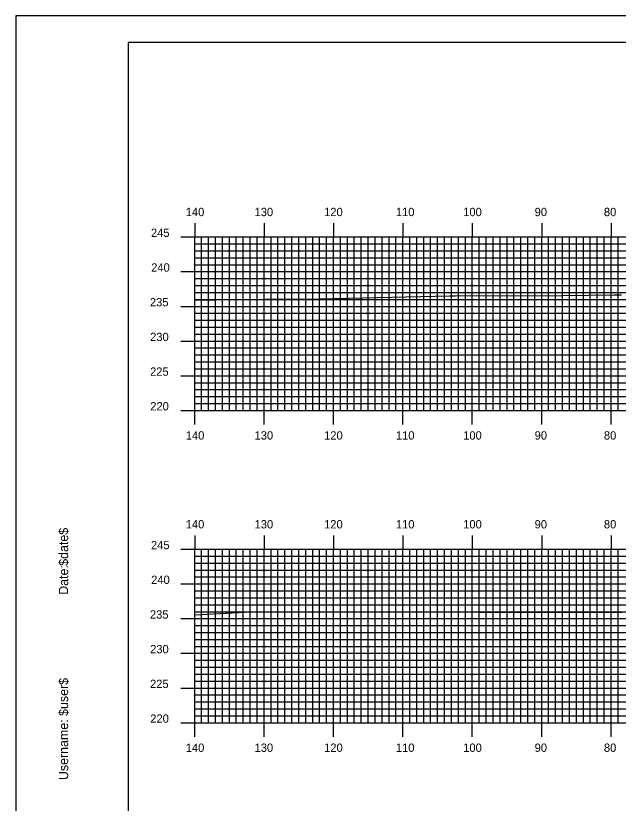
# Model space of a CAD drawing. Extents: x 1802716 to 1803060, y 442591 to 442811.
# Drawn here: x 1802716.3 to 1802803.1, y 442697.1 to 442810.5 of the extents above; entities that cross this region are included whole.
import ezdxf

# ---------------------------------------------------------------- set-up
doc = ezdxf.new("R2010")
doc.units = 0
for name, color, linetype in [('BORDER', 7, 'Continuous'), ('H_V ANNOTATION', 7, 'Continuous'), ('MAJOR', 7, 'Continuous'), ('MINOR', 7, 'Continuous'), ('PLOT BOUNDARY', 7, 'Continuous'), ('S_Roadway_Centerline', 7, 'Continuous')]:
    doc.layers.add(name, color=color, linetype=linetype)

msp = doc.modelspace()

# ---------------------------------------------------------------- linework, layer by layer
at = {"layer": 'BORDER'}
msp.add_lwpolyline([(1802732.51, 442596.67), (1803052.51, 442596.67), (1803052.51, 442806.67), (1802732.51, 442806.67)], close=True, dxfattribs=at)
at = {"layer": 'MAJOR'}
for p, q in [((1802742.11, 442780.67), (1802742.11, 442778.67)), ((1802752.11, 442780.67), (1802752.11, 442778.67)), ((1802762.11, 442780.67), (1802762.11, 442778.67)), ((1802772.11, 442780.67), (1802772.11, 442778.67)), ((1802782.11, 442780.67), (1802782.11, 442778.67)), ((1802792.11, 442780.67), (1802792.11, 442778.67)), ((1802802.11, 442780.67), (1802802.11, 442778.67)), ((1802740.11, 442778.67), (1802742.11, 442778.67)), ((1802742.11, 442778.67), (1803022.11, 442778.67)), ((1802742.11, 442753.67), (1802742.11, 442778.67)), ((1802742.11, 442753.67), (1802742.11, 442778.67)), ((1802742.11, 442778.67), (1803022.11, 442778.67)), ((1802752.11, 442753.67), (1802752.11, 442778.67)), ((1802762.11, 442753.67), (1802762.11, 442778.67)), ((1802772.11, 442753.67), (1802772.11, 442778.67)), ((1802782.11, 442753.67), (1802782.11, 442778.67)), ((1802792.11, 442753.67), (1802792.11, 442778.67)), ((1802802.11, 442753.67), (1802802.11, 442778.67)), ((1802740.11, 442773.67), (1802742.11, 442773.67)), ((1802742.11, 442773.67), (1803022.11, 442773.67)), ((1802740.11, 442768.67), (1802742.11, 442768.67)), ((1802742.11, 442768.67), (1803022.11, 442768.67)), ((1802740.11, 442763.67), (1802742.11, 442763.67)), ((1802742.11, 442763.67), (1803022.11, 442763.67)), ((1802740.11, 442758.67), (1802742.11, 442758.67)), ((1802742.11, 442758.67), (1803022.11, 442758.67)), ((1802740.11, 442753.67), (1802742.11, 442753.67)), ((1802742.11, 442753.67), (1803022.11, 442753.67)), ((1802742.11, 442753.67), (1803022.11, 442753.67)), ((1802742.11, 442751.66), (1802742.11, 442753.67)), ((1802752.11, 442751.66), (1802752.11, 442753.67)), ((1802762.11, 442751.66), (1802762.11, 442753.67)), ((1802772.11, 442751.66), (1802772.11, 442753.67)), ((1802782.11, 442751.66), (1802782.11, 442753.67)), ((1802792.11, 442751.66), (1802792.11, 442753.67)), ((1802802.11, 442751.66), (1802802.11, 442753.67)), ((1802742.11, 442735.67), (1802742.11, 442733.67)), ((1802752.11, 442735.67), (1802752.11, 442733.67)), ((1802762.11, 442735.67), (1802762.11, 442733.67)), ((1802772.11, 442735.67), (1802772.11, 442733.67)), ((1802782.11, 442735.67), (1802782.11, 442733.67)), ((1802792.11, 442735.67), (1802792.11, 442733.67)), ((1802802.11, 442735.67), (1802802.11, 442733.67)), ((1802740.11, 442733.67), (1802742.11, 442733.67)), ((1802742.11, 442733.67), (1803022.11, 442733.67)), ((1802742.11, 442708.67), (1802742.11, 442733.67)), ((1802742.11, 442708.67), (1802742.11, 442733.67)), ((1802742.11, 442733.67), (1803022.11, 442733.67)), ((1802752.11, 442708.67), (1802752.11, 442733.67)), ((1802762.11, 442708.67), (1802762.11, 442733.67)), ((1802772.11, 442708.67), (1802772.11, 442733.67)), ((1802782.11, 442708.67), (1802782.11, 442733.67)), ((1802792.11, 442708.67), (1802792.11, 442733.67)), ((1802802.11, 442708.67), (1802802.11, 442733.67)), ((1802740.11, 442728.67), (1802742.11, 442728.67)), ((1802742.11, 442728.67), (1803022.11, 442728.67)), ((1802740.11, 442723.67), (1802742.11, 442723.67)), ((1802742.11, 442723.67), (1803022.11, 442723.67)), ((1802740.11, 442718.67), (1802742.11, 442718.67)), ((1802742.11, 442718.67), (1803022.11, 442718.67)), ((1802740.11, 442713.67), (1802742.11, 442713.67)), ((1802742.11, 442713.67), (1803022.11, 442713.67)), ((1802740.11, 442708.67), (1802742.11, 442708.67)), ((1802742.11, 442708.67), (1803022.11, 442708.67)), ((1802742.11, 442708.67), (1803022.11, 442708.67)), ((1802742.11, 442706.66), (1802742.11, 442708.67)), ((1802752.11, 442706.66), (1802752.11, 442708.67)), ((1802762.11, 442706.66), (1802762.11, 442708.67)), ((1802772.11, 442706.66), (1802772.11, 442708.67)), ((1802782.11, 442706.66), (1802782.11, 442708.67)), ((1802792.11, 442706.66), (1802792.11, 442708.67)), ((1802802.11, 442706.66), (1802802.11, 442708.67))]:
    msp.add_line(p, q, dxfattribs=at)
at = {"layer": 'MINOR'}
for p, q in [((1802743.11, 442753.67), (1802743.11, 442778.67)), ((1802744.11, 442753.67), (1802744.11, 442778.67)), ((1802745.11, 442753.67), (1802745.11, 442778.67)), ((1802746.11, 442753.67), (1802746.11, 442778.67)), ((1802747.11, 442753.67), (1802747.11, 442778.67)), ((1802748.11, 442753.67), (1802748.11, 442778.67)), ((1802749.11, 442753.67), (1802749.11, 442778.67)), ((1802750.11, 442753.67), (1802750.11, 442778.67)), ((1802751.11, 442753.67), (1802751.11, 442778.67)), ((1802753.11, 442753.67), (1802753.11, 442778.67)), ((1802754.11, 442753.67), (1802754.11, 442778.67)), ((1802755.11, 442753.67), (1802755.11, 442778.67)), ((1802756.11, 442753.67), (1802756.11, 442778.67)), ((1802757.11, 442753.67), (1802757.11, 442778.67)), ((1802758.11, 442753.67), (1802758.11, 442778.67)), ((1802759.11, 442753.67), (1802759.11, 442778.67)), ((1802760.11, 442753.67), (1802760.11, 442778.67)), ((1802761.11, 442753.67), (1802761.11, 442778.67)), ((1802763.11, 442753.67), (1802763.11, 442778.67)), ((1802764.11, 442753.67), (1802764.11, 442778.67)), ((1802765.11, 442753.67), (1802765.11, 442778.67)), ((1802766.11, 442753.67), (1802766.11, 442778.67)), ((1802767.11, 442753.67), (1802767.11, 442778.67)), ((1802768.11, 442753.67), (1802768.11, 442778.67)), ((1802769.11, 442753.67), (1802769.11, 442778.67)), ((1802770.11, 442753.67), (1802770.11, 442778.67)), ((1802771.11, 442753.67), (1802771.11, 442778.67)), ((1802773.11, 442753.67), (1802773.11, 442778.67)), ((1802774.11, 442753.67), (1802774.11, 442778.67)), ((1802775.11, 442753.67), (1802775.11, 442778.67)), ((1802776.11, 442753.67), (1802776.11, 442778.67)), ((1802777.11, 442753.67), (1802777.11, 442778.67)), ((1802778.11, 442753.67), (1802778.11, 442778.67)), ((1802779.11, 442753.67), (1802779.11, 442778.67)), ((1802780.11, 442753.67), (1802780.11, 442778.67)), ((1802781.11, 442753.67), (1802781.11, 442778.67)), ((1802783.11, 442753.67), (1802783.11, 442778.67)), ((1802784.11, 442753.67), (1802784.11, 442778.67)), ((1802785.11, 442753.67), (1802785.11, 442778.67)), ((1802786.11, 442753.67), (1802786.11, 442778.67)), ((1802787.11, 442753.67), (1802787.11, 442778.67)), ((1802788.11, 442753.67), (1802788.11, 442778.67)), ((1802789.11, 442753.67), (1802789.11, 442778.67)), ((1802790.11, 442753.67), (1802790.11, 442778.67)), ((1802791.11, 442753.67), (1802791.11, 442778.67)), ((1802793.11, 442753.67), (1802793.11, 442778.67)), ((1802794.11, 442753.67), (1802794.11, 442778.67)), ((1802795.11, 442753.67), (1802795.11, 442778.67)), ((1802796.11, 442753.67), (1802796.11, 442778.67)), ((1802797.11, 442753.67), (1802797.11, 442778.67)), ((1802798.11, 442753.67), (1802798.11, 442778.67)), ((1802799.11, 442753.67), (1802799.11, 442778.67)), ((1802800.11, 442753.67), (1802800.11, 442778.67)), ((1802801.11, 442753.67), (1802801.11, 442778.67)), ((1802803.11, 442753.67), (1802803.11, 442778.67)), ((1802742.11, 442777.67), (1803022.11, 442777.67)), ((1802742.11, 442777.67), (1802744.12, 442777.67)), ((1802742.11, 442776.67), (1803022.11, 442776.67)), ((1802742.11, 442776.67), (1802744.12, 442776.67)), ((1802742.11, 442775.67), (1803022.11, 442775.67)), ((1802742.11, 442775.67), (1802744.12, 442775.67)), ((1802742.11, 442774.67), (1803022.11, 442774.67)), ((1802742.11, 442774.67), (1802744.12, 442774.67)), ((1802742.11, 442772.67), (1803022.11, 442772.67)), ((1802742.11, 442772.67), (1802744.12, 442772.67)), ((1802742.11, 442771.67), (1803022.11, 442771.67)), ((1802742.11, 442771.67), (1802744.12, 442771.67)), ((1802742.11, 442770.67), (1803022.11, 442770.67)), ((1802742.11, 442770.67), (1802744.12, 442770.67)), ((1802742.11, 442769.67), (1803022.11, 442769.67)), ((1802742.11, 442769.67), (1802744.12, 442769.67)), ((1802742.11, 442767.67), (1803022.11, 442767.67)), ((1802742.11, 442767.67), (1802744.12, 442767.67)), ((1802742.11, 442766.67), (1803022.11, 442766.67)), ((1802742.11, 442766.67), (1802744.12, 442766.67)), ((1802742.11, 442765.67), (1803022.11, 442765.67)), ((1802742.11, 442765.67), (1802744.12, 442765.67)), ((1802742.11, 442764.67), (1803022.11, 442764.67)), ((1802742.11, 442764.67), (1802744.12, 442764.67)), ((1802742.11, 442762.67), (1803022.11, 442762.67)), ((1802742.11, 442762.67), (1802744.12, 442762.67)), ((1802742.11, 442761.67), (1803022.11, 442761.67)), ((1802742.11, 442761.67), (1802744.12, 442761.67)), ((1802742.11, 442760.67), (1803022.11, 442760.67)), ((1802742.11, 442760.67), (1802744.12, 442760.67)), ((1802742.11, 442759.67), (1803022.11, 442759.67)), ((1802742.11, 442759.67), (1802744.12, 442759.67)), ((1802742.11, 442757.67), (1803022.11, 442757.67)), ((1802742.11, 442757.67), (1802744.12, 442757.67)), ((1802742.11, 442756.67), (1803022.11, 442756.67)), ((1802742.11, 442756.67), (1802744.12, 442756.67)), ((1802742.11, 442755.67), (1803022.11, 442755.67)), ((1802742.11, 442755.67), (1802744.12, 442755.67)), ((1802742.11, 442754.67), (1803022.11, 442754.67)), ((1802742.11, 442754.67), (1802744.12, 442754.67)), ((1802742.11, 442732.67), (1803022.11, 442732.67)), ((1802742.11, 442732.67), (1802744.12, 442732.67)), ((1802743.11, 442708.67), (1802743.11, 442733.67)), ((1802744.11, 442708.67), (1802744.11, 442733.67)), ((1802745.11, 442708.67), (1802745.11, 442733.67)), ((1802746.11, 442708.67), (1802746.11, 442733.67)), ((1802747.11, 442708.67), (1802747.11, 442733.67)), ((1802748.11, 442708.67), (1802748.11, 442733.67)), ((1802749.11, 442708.67), (1802749.11, 442733.67)), ((1802750.11, 442708.67), (1802750.11, 442733.67)), ((1802751.11, 442708.67), (1802751.11, 442733.67)), ((1802753.11, 442708.67), (1802753.11, 442733.67)), ((1802754.11, 442708.67), (1802754.11, 442733.67)), ((1802755.11, 442708.67), (1802755.11, 442733.67)), ((1802756.11, 442708.67), (1802756.11, 442733.67)), ((1802757.11, 442708.67), (1802757.11, 442733.67)), ((1802758.11, 442708.67), (1802758.11, 442733.67)), ((1802759.11, 442708.67), (1802759.11, 442733.67)), ((1802760.11, 442708.67), (1802760.11, 442733.67)), ((1802761.11, 442708.67), (1802761.11, 442733.67)), ((1802763.11, 442708.67), (1802763.11, 442733.67)), ((1802764.11, 442708.67), (1802764.11, 442733.67)), ((1802765.11, 442708.67), (1802765.11, 442733.67)), ((1802766.11, 442708.67), (1802766.11, 442733.67)), ((1802767.11, 442708.67), (1802767.11, 442733.67)), ((1802768.11, 442708.67), (1802768.11, 442733.67)), ((1802769.11, 442708.67), (1802769.11, 442733.67)), ((1802770.11, 442708.67), (1802770.11, 442733.67)), ((1802771.11, 442708.67), (1802771.11, 442733.67)), ((1802773.11, 442708.67), (1802773.11, 442733.67)), ((1802774.11, 442708.67), (1802774.11, 442733.67)), ((1802775.11, 442708.67), (1802775.11, 442733.67)), ((1802776.11, 442708.67), (1802776.11, 442733.67)), ((1802777.11, 442708.67), (1802777.11, 442733.67)), ((1802778.11, 442708.67), (1802778.11, 442733.67)), ((1802779.11, 442708.67), (1802779.11, 442733.67)), ((1802780.11, 442708.67), (1802780.11, 442733.67)), ((1802781.11, 442708.67), (1802781.11, 442733.67)), ((1802783.11, 442708.67), (1802783.11, 442733.67)), ((1802784.11, 442708.67), (1802784.11, 442733.67)), ((1802785.11, 442708.67), (1802785.11, 442733.67)), ((1802786.11, 442708.67), (1802786.11, 442733.67)), ((1802787.11, 442708.67), (1802787.11, 442733.67)), ((1802788.11, 442708.67), (1802788.11, 442733.67)), ((1802789.11, 442708.67), (1802789.11, 442733.67)), ((1802790.11, 442708.67), (1802790.11, 442733.67)), ((1802791.11, 442708.67), (1802791.11, 442733.67)), ((1802793.11, 442708.67), (1802793.11, 442733.67)), ((1802794.11, 442708.67), (1802794.11, 442733.67)), ((1802795.11, 442708.67), (1802795.11, 442733.67)), ((1802796.11, 442708.67), (1802796.11, 442733.67)), ((1802797.11, 442708.67), (1802797.11, 442733.67)), ((1802798.11, 442708.67), (1802798.11, 442733.67)), ((1802799.11, 442708.67), (1802799.11, 442733.67)), ((1802800.11, 442708.67), (1802800.11, 442733.67)), ((1802801.11, 442708.67), (1802801.11, 442733.67)), ((1802803.11, 442708.67), (1802803.11, 442733.67)), ((1802742.11, 442731.67), (1803022.11, 442731.67)), ((1802742.11, 442731.67), (1802744.12, 442731.67)), ((1802742.11, 442730.67), (1803022.11, 442730.67)), ((1802742.11, 442730.67), (1802744.12, 442730.67)), ((1802742.11, 442729.67), (1803022.11, 442729.67)), ((1802742.11, 442729.67), (1802744.12, 442729.67)), ((1802742.11, 442727.67), (1803022.11, 442727.67)), ((1802742.11, 442727.67), (1802744.12, 442727.67)), ((1802742.11, 442726.67), (1803022.11, 442726.67)), ((1802742.11, 442726.67), (1802744.12, 442726.67)), ((1802742.11, 442725.67), (1803022.11, 442725.67)), ((1802742.11, 442725.67), (1802744.12, 442725.67)), ((1802742.11, 442724.67), (1803022.11, 442724.67)), ((1802742.11, 442724.67), (1802744.12, 442724.67)), ((1802742.11, 442722.67), (1803022.11, 442722.67)), ((1802742.11, 442722.67), (1802744.12, 442722.67)), ((1802742.11, 442721.67), (1803022.11, 442721.67)), ((1802742.11, 442721.67), (1802744.12, 442721.67)), ((1802742.11, 442720.67), (1803022.11, 442720.67)), ((1802742.11, 442720.67), (1802744.12, 442720.67)), ((1802742.11, 442719.67), (1803022.11, 442719.67)), ((1802742.11, 442719.67), (1802744.12, 442719.67)), ((1802742.11, 442717.67), (1803022.11, 442717.67)), ((1802742.11, 442717.67), (1802744.12, 442717.67)), ((1802742.11, 442716.67), (1803022.11, 442716.67)), ((1802742.11, 442716.67), (1802744.12, 442716.67)), ((1802742.11, 442715.67), (1803022.11, 442715.67)), ((1802742.11, 442715.67), (1802744.12, 442715.67)), ((1802742.11, 442714.67), (1803022.11, 442714.67)), ((1802742.11, 442714.67), (1802744.12, 442714.67)), ((1802742.11, 442712.67), (1803022.11, 442712.67)), ((1802742.11, 442712.67), (1802744.12, 442712.67)), ((1802742.11, 442711.67), (1803022.11, 442711.67)), ((1802742.11, 442711.67), (1802744.12, 442711.67)), ((1802742.11, 442710.67), (1803022.11, 442710.67)), ((1802742.11, 442710.67), (1802744.12, 442710.67)), ((1802742.11, 442709.67), (1803022.11, 442709.67)), ((1802742.11, 442709.67), (1802744.12, 442709.67))]:
    msp.add_line(p, q, dxfattribs=at)
at = {"layer": 'PLOT BOUNDARY'}
msp.add_lwpolyline([(1802716.33, 442590.55), (1803056.33, 442590.55), (1803056.33, 442810.55), (1802716.33, 442810.55)], close=True, dxfattribs=at)
at = {"layer": 'S_Roadway_Centerline'}
for points in [[(1802742.11, 442769.59), (1802745.21, 442769.59), (1802752.29, 442769.69), (1802760.11, 442769.76), (1802778.83, 442770.19), (1802779.67, 442770.2), (1802780.45, 442770.22), (1802791.46, 442770.2), (1802802.53, 442770.33), (1802803.04, 442770.34), (1802803.62, 442770.34)], [(1802742.11, 442724.22), (1802750.22, 442724.63), (1802761.09, 442724.64), (1802761.26, 442724.64), (1802761.46, 442724.64), (1802772.86, 442724.65), (1802783.17, 442724.6), (1802787.46, 442724.56), (1802803.66, 442724.59)]]:
    msp.add_lwpolyline(points, dxfattribs=at)

# ---------------------------------------------------------------- texts
at = {"layer": 'BORDER'}
for s, p in [('$date$', (1802723.88, 442731.28)), ('Date:', (1802723.88, 442727.1)), ('$user$', (1802723.88, 442709.65)), ('Username:', (1802723.88, 442700.4))]:
    msp.add_text(s, height=1.339, rotation=90, dxfattribs=at).set_placement(p)
at = {"layer": 'H_V ANNOTATION'}
for s, p in [('140', (1802740.82, 442781.67)), ('130', (1802750.74, 442781.67)), ('120', (1802760.76, 442781.67)), ('110', (1802771.1, 442781.67)), ('100', (1802780.8, 442781.67)), ('90', (1802791.09, 442781.67)), ('80', (1802801.07, 442781.67)), ('245', (1802735.81, 442778.67)), ('240', (1802735.84, 442773.67)), ('235', (1802735.66, 442768.67)), ('230', (1802735.69, 442763.67)), ('225', (1802735.68, 442758.67)), ('220', (1802735.71, 442753.67)), ('140', (1802740.82, 442749.47)), ('130', (1802750.74, 442749.47)), ('120', (1802760.76, 442749.47)), ('110', (1802771.1, 442749.47)), ('100', (1802780.8, 442749.47)), ('90', (1802791.09, 442749.47)), ('80', (1802801.07, 442749.47)), ('140', (1802740.82, 442736.67)), ('130', (1802750.74, 442736.67)), ('120', (1802760.76, 442736.67)), ('110', (1802771.1, 442736.67)), ('100', (1802780.8, 442736.67)), ('90', (1802791.09, 442736.67)), ('80', (1802801.07, 442736.67)), ('245', (1802735.81, 442733.67)), ('240', (1802735.84, 442728.67)), ('235', (1802735.66, 442723.67)), ('230', (1802735.69, 442718.67)), ('225', (1802735.68, 442713.67)), ('220', (1802735.71, 442708.67)), ('140', (1802740.82, 442704.47)), ('130', (1802750.74, 442704.47)), ('120', (1802760.76, 442704.47)), ('110', (1802771.1, 442704.47)), ('100', (1802780.8, 442704.47)), ('90', (1802791.09, 442704.47)), ('80', (1802801.07, 442704.47))]:
    msp.add_text(s, height=1.2, dxfattribs=at).set_placement(p)
at = {"layer": 'MAJOR'}
for p in [(1802742.11, 442753.67), (1802742.11, 442708.67)]:
    msp.add_text('-', height=0.012, dxfattribs=at).set_placement(p)

doc.saveas('drawing.dxf')
